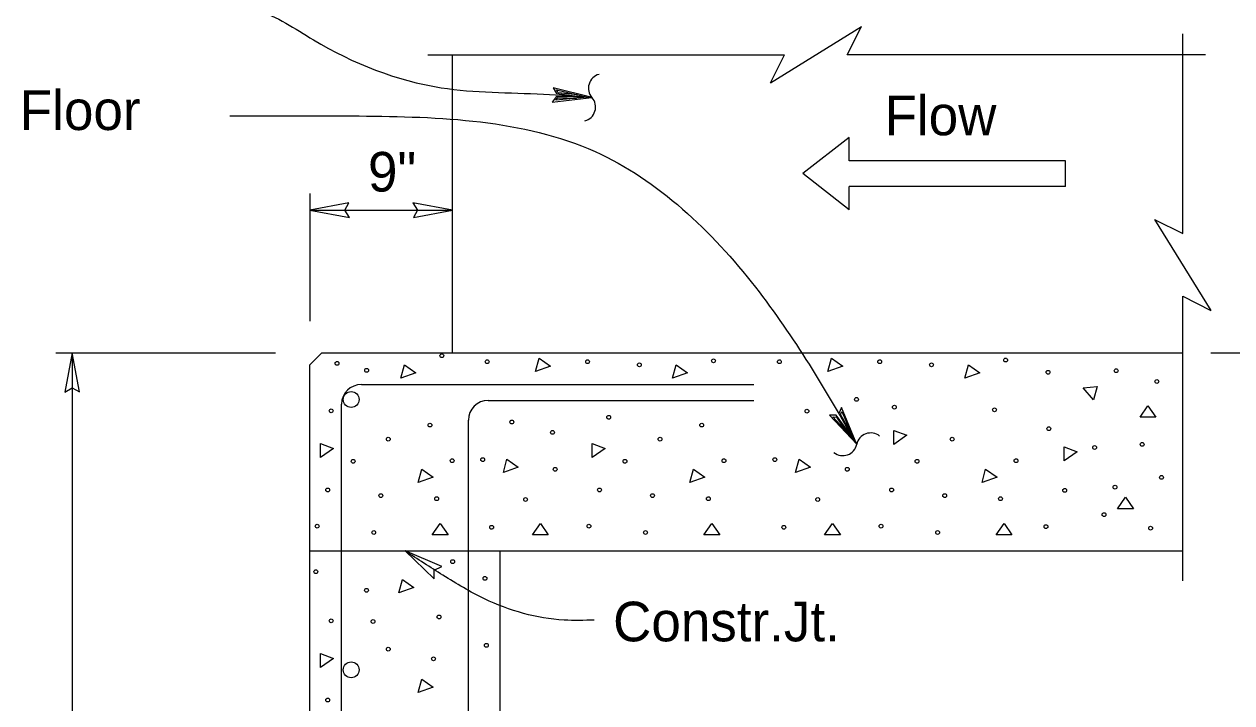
# Model space of a CAD drawing. Extents: x -0.08 to 2.83, y -0.03 to 1.92.
# Drawn here: x 1.203 to 1.5998, y 0.9512 to 1.1742 of the extents above; entities that cross this region are included whole.
import ezdxf

# ---------------------------------------------------------------- set-up
doc = ezdxf.new("R2010")
doc.units = 0
for name, color, linetype in [('50', 7, 'Continuous'), ('51', 7, 'Continuous'), ('54', 7, 'Continuous'), ('55', 7, 'Continuous'), ('57', 7, 'Continuous')]:
    doc.layers.add(name, color=color, linetype=linetype)

msp = doc.modelspace()

# ---------------------------------------------------------------- linework, layer by layer
at = {"layer": '50'}
for p, q in [((1.343748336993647, 1.066219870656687), (1.343748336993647, 1.1641173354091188)), ((1.300779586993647, 1.066219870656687), (1.296873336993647, 1.062313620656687)), ((1.300779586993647, 1.066219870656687), (1.5836677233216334, 1.066219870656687)), ((1.3710588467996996, 1.0600765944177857), (1.3722255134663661, 1.0644765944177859)), ((1.3722255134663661, 1.0644765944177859), (1.3759588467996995, 1.0618515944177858)), ((1.4670538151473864, 1.0600765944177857), (1.4682204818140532, 1.0644765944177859)), ((1.4682204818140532, 1.0644765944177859), (1.4719538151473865, 1.0618515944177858)), ((1.296873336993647, 0.6912198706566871), (1.296873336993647, 1.062313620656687)), ((1.3267968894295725, 1.0578507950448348), (1.327963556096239, 1.062250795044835)), ((1.3316968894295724, 1.059625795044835), (1.3267968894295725, 1.0578507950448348)), ((1.327963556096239, 1.062250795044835), (1.3316968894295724, 1.059625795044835)), ((1.3759588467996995, 1.0618515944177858), (1.3710588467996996, 1.0600765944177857)), ((1.4160789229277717, 1.0578507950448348), (1.4172455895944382, 1.062250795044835)), ((1.4209789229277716, 1.059625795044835), (1.4160789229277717, 1.0578507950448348)), ((1.4172455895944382, 1.062250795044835), (1.4209789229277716, 1.059625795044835)), ((1.4719538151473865, 1.0618515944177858), (1.4670538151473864, 1.0600765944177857)), ((1.5120738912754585, 1.0578507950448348), (1.5132405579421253, 1.062250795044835)), ((1.5169738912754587, 1.059625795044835), (1.5120738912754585, 1.0578507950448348)), ((1.5132405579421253, 1.062250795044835), (1.5169738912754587, 1.059625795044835)), ((1.551007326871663, 1.0547551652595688), (1.5555489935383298, 1.0551634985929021)), ((1.55434899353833, 1.0507634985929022), (1.551007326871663, 1.0547551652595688)), ((1.5555489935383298, 1.0551634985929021), (1.55434899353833, 1.0507634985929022)), ((1.5696571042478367, 1.045088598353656), (1.5722571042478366, 1.0488302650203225)), ((1.5722571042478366, 1.0488302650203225), (1.57486543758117, 1.045088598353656)), ((1.57486543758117, 1.045088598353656), (1.5696571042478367, 1.045088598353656)), ((1.4887533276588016, 1.0361190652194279), (1.488736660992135, 1.040677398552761)), ((1.488736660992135, 1.040677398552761), (1.4930199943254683, 1.0391023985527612)), ((1.3003828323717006, 1.0318357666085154), (1.300366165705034, 1.0363940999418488)), ((1.300366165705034, 1.0363940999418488), (1.3046494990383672, 1.0348190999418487)), ((1.3896648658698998, 1.0318357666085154), (1.389648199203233, 1.0363940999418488)), ((1.389648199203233, 1.0363940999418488), (1.3939315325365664, 1.0348190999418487)), ((1.4930199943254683, 1.0391023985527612), (1.4887533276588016, 1.0361190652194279)), ((1.3046494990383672, 1.0348190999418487), (1.3003828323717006, 1.0318357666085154)), ((1.3939315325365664, 1.0348190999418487), (1.3896648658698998, 1.0318357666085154)), ((1.5447260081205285, 1.0307487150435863), (1.5447093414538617, 1.0353070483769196)), ((1.5447093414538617, 1.0353070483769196), (1.5489926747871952, 1.0337320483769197)), ((1.5489926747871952, 1.0337320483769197), (1.5447260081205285, 1.0307487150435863)), ((1.3324829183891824, 1.0236061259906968), (1.333649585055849, 1.0280061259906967)), ((1.333649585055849, 1.0280061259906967), (1.3373829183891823, 1.0253811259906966)), ((1.360448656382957, 1.0268600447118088), (1.3616153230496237, 1.0312683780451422)), ((1.3653403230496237, 1.0286433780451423), (1.360448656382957, 1.0268600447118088)), ((1.3616153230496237, 1.0312683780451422), (1.3653403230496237, 1.0286433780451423)), ((1.4217649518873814, 1.0236061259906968), (1.4229316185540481, 1.0280061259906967)), ((1.4229316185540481, 1.0280061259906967), (1.4266649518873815, 1.0253811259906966)), ((1.456443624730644, 1.0268600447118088), (1.4576102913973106, 1.0312683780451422)), ((1.4613352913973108, 1.0286433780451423), (1.456443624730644, 1.0268600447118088)), ((1.4576102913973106, 1.0312683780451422), (1.4613352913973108, 1.0286433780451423)), ((1.5177599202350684, 1.0236061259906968), (1.5189265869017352, 1.0280061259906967)), ((1.5189265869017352, 1.0280061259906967), (1.5226599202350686, 1.0253811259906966)), ((1.3373829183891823, 1.0253811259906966), (1.3324829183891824, 1.0236061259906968)), ((1.4266649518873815, 1.0253811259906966), (1.4217649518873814, 1.0236061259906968)), ((1.5226599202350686, 1.0253811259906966), (1.5177599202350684, 1.0236061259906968)), ((1.5622480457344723, 1.0149934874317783), (1.5648480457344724, 1.018735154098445)), ((1.5648480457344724, 1.018735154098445), (1.5674563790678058, 1.0149934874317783)), ((1.5674563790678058, 1.0149934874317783), (1.5622480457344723, 1.0149934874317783)), ((1.3370938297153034, 1.0064281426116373), (1.3396938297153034, 1.010169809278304)), ((1.3396938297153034, 1.010169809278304), (1.3423021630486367, 1.0064281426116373)), ((1.3700158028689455, 1.0064281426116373), (1.3726158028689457, 1.010169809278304)), ((1.3726158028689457, 1.010169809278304), (1.375224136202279, 1.0064281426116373)), ((1.4263758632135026, 1.0064281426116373), (1.4289758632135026, 1.010169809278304)), ((1.4289758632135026, 1.010169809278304), (1.4315841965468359, 1.0064281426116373)), ((1.4660107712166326, 1.0064281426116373), (1.4686107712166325, 1.010169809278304)), ((1.4686107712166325, 1.010169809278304), (1.471219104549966, 1.0064281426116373)), ((1.5223708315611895, 1.0064281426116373), (1.5249708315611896, 1.010169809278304)), ((1.5249708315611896, 1.010169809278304), (1.527579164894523, 1.0064281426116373)), ((1.3423021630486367, 1.0064281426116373), (1.3370938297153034, 1.0064281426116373)), ((1.375224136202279, 1.0064281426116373), (1.3700158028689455, 1.0064281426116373)), ((1.4315841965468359, 1.0064281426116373), (1.4263758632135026, 1.0064281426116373)), ((1.471219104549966, 1.0064281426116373), (1.4660107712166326, 1.0064281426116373)), ((1.527579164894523, 1.0064281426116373), (1.5223708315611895, 1.0064281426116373)), ((1.296873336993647, 1.0011157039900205), (1.359373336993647, 1.0011157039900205)), ((1.359373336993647, 1.0011157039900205), (1.5836677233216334, 1.0011157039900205)), ((1.3593733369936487, 0.6912198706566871), (1.359373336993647, 1.0011157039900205)), ((1.3261489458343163, 0.9873208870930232), (1.3273156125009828, 0.9917208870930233)), ((1.3310489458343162, 0.9890958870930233), (1.3261489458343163, 0.9873208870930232)), ((1.3273156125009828, 0.9917208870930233), (1.3310489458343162, 0.9890958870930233)), ((1.3003828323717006, 0.9628270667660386), (1.300366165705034, 0.9673854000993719)), ((1.300366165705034, 0.9673854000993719), (1.3046494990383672, 0.9658104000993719)), ((1.3046494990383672, 0.9658104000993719), (1.3003828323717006, 0.9628270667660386)), ((1.3324829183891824, 0.9545974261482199), (1.333649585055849, 0.9589974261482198)), ((1.3373829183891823, 0.9563724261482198), (1.3324829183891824, 0.9545974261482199)), ((1.333649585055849, 0.9589974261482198), (1.3373829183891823, 0.9563724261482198))]:
    msp.add_line(p, q, dxfattribs=at)
for centre in [(1.3402182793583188, 1.0652488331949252), (1.3551425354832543, 1.0632739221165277), (1.3881219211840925, 1.0632960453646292), (1.429500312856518, 1.0635831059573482), (1.451137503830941, 1.0632739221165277), (1.4841168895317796, 1.0632960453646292), (1.5254952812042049, 1.0638210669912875), (1.30579344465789, 1.062745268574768), (1.3155124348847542, 1.0604525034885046), (1.4051387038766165, 1.0622425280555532), (1.5011336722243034, 1.0622425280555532), (1.5394304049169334, 1.0598250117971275), (1.5618039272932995, 1.0603175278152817), (1.575196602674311, 1.0567696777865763), (1.3038938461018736, 1.0471677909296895), (1.4601979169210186, 1.0470488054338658), (1.4764870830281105, 1.0509084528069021), (1.4889328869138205, 1.0483575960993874), (1.5218510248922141, 1.0474613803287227), (1.3632511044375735, 1.043479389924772), (1.3950795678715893, 1.0450261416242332), (1.3363360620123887, 1.0424641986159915), (1.376620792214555, 1.0400687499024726), (1.425618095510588, 1.0424641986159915), (1.5396757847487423, 1.0412755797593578), (1.3226443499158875, 1.0378605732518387), (1.4119263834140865, 1.0378605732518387), (1.5079213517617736, 1.0378605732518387), (1.570359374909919, 1.0361384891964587), (1.5547346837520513, 1.0350952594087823), (1.3111190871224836, 1.0305680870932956), (1.3436425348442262, 1.0307534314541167), (1.3536722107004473, 1.031114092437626), (1.3774622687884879, 1.0279488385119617), (1.4004011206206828, 1.0305680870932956), (1.4329245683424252, 1.0307534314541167), (1.4496671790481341, 1.031114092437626), (1.473457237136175, 1.0279488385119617), (1.4963960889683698, 1.0305680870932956), (1.5289195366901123, 1.0307534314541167), (1.576712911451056, 1.0252881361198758), (1.302741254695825, 1.0211511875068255), (1.320187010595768, 1.0192954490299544), (1.3920232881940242, 1.0211511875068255), (1.4094690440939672, 1.0192954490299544), (1.4880182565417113, 1.0211511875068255), (1.5054640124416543, 1.0192954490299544), (1.5449010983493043, 1.0210183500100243), (1.5614318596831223, 1.0220731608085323), (1.33853635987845, 1.0182701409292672), (1.367750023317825, 1.0180243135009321), (1.427818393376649, 1.0182701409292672), (1.463744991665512, 1.0180243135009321), (1.5238133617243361, 1.0182701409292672), (1.5578386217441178, 1.0130502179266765), (1.2992845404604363, 1.0092635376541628), (1.356594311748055, 1.0088822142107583), (1.3885665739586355, 1.0092635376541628), (1.452589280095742, 1.0088822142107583), (1.4845615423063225, 1.0092635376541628), (1.5387270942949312, 1.0091102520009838), (1.5731228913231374, 1.0085992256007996), (1.3178671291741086, 1.0071898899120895), (1.4071491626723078, 1.0071898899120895), (1.503144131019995, 1.0071898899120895), (1.3437926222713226, 0.9976017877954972), (1.2988398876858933, 0.9942873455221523), (1.3544017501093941, 0.9921030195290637), (1.3154833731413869, 0.9881943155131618), (1.3038938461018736, 0.9781590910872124), (1.3176366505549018, 0.9779584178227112), (1.339322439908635, 0.9794282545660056), (1.3226443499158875, 0.9688518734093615), (1.354863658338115, 0.9701051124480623), (1.3374831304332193, 0.9656643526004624), (1.302741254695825, 0.9521424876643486)]:
    msp.add_circle(centre, 0.0006257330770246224, dxfattribs=at)
at = {"layer": '51'}
for p, q in [((1.3138004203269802, 1.0558032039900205), (1.4427066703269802, 1.0558032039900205)), ((1.3072900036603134, 0.7120532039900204), (1.3072900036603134, 1.0492927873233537)), ((1.3554670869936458, 1.050594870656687), (1.4427066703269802, 1.050594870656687)), ((1.3489566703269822, 0.7120532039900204), (1.3489566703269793, 1.0440844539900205))]:
    msp.add_line(p, q, dxfattribs=at)
for centre in [(1.310454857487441, 1.0508614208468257), (1.310454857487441, 0.9620534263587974)]:
    msp.add_circle(centre, 0.002604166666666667, dxfattribs=at)
for centre in [(1.3138004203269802, 1.0492927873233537), (1.3554670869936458, 1.0440844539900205)]:
    msp.add_arc(centre, 0.006510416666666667, 90, 180, dxfattribs=at)
at = {"layer": '54'}
for points in [[(1.296873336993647, 1.113094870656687), (1.3098650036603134, 1.110719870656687), (1.3083566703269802, 1.113094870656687), (1.3097150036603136, 1.1154948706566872)], [(1.343748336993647, 1.113094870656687), (1.3307566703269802, 1.115469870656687), (1.3322650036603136, 1.113094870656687), (1.3309066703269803, 1.110694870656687)], [(1.218748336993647, 1.066219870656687), (1.216373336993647, 1.0532282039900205), (1.218748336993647, 1.0547365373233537), (1.2211483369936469, 1.0533782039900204)], [(1.3281555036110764, 1.0011157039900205), (1.337686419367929, 0.9919731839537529), (1.3377369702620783, 0.9947862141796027), (1.3401931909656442, 0.9960400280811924)]]:
    msp.add_lwpolyline(points, close=True, dxfattribs=at)
at = {"layer": '55'}
for p, q in [((1.4482468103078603, 1.1548715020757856), (1.4780801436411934, 1.1733694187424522)), ((1.4734582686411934, 1.1641173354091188), (1.4780801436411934, 1.1733694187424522)), ((1.5836677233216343, 1.1053734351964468), (1.5836677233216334, 1.1710349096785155)), ((1.3356639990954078, 1.1641173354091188), (1.4528718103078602, 1.1641173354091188)), ((1.4482468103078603, 1.1548715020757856), (1.4528718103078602, 1.1641173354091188)), ((1.59117128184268, 1.1641173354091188), (1.4734582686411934, 1.1641173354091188)), ((1.296873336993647, 1.1185363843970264), (1.296873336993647, 1.0765891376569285)), ((1.296873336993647, 1.113094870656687), (1.343748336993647, 1.113094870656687)), ((1.5744218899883, 1.1099984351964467), (1.5836677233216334, 1.1053734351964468)), ((1.5744218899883, 1.1099984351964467), (1.5929198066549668, 1.0801651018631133)), ((1.5836677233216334, 0.9912447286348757), (1.5836677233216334, 1.0847869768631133)), ((1.5836677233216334, 1.0847869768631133), (1.5929198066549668, 1.0801651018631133)), ((1.2133483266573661, 1.066219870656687), (1.285620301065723, 1.066219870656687)), ((1.218748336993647, 1.066219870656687), (1.2187483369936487, 0.6912198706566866)), ((1.5929198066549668, 1.066219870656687), (1.635836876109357, 1.066219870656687))]:
    msp.add_line(p, q, dxfattribs=at)
for points in [[(1.3895995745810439, 1.1500559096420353), (1.3768599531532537, 1.1533016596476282), (1.3778866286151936, 1.1513594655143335), (1.3865895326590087, 1.1502558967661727), (1.3777920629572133, 1.150355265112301), (1.3765153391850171, 1.1485641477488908), (1.3895740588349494, 1.1500493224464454)], [(1.384824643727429, 1.1509460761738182), (1.3785082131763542, 1.1516505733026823), (1.377945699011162, 1.1525749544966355), (1.3881530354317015, 1.1501560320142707), (1.3777008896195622, 1.1491587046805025), (1.3784037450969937, 1.150020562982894), (1.3844869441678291, 1.1498083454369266)], [(1.4766006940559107, 1.0361355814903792), (1.4715697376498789, 1.0482814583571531), (1.4706293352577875, 1.0462960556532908), (1.4749580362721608, 1.0386658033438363), (1.4697685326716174, 1.0457703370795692), (1.4675695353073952, 1.045719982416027), (1.476580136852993, 1.0361520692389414)], [(1.4744536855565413, 1.0404924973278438), (1.4712347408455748, 1.0459726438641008), (1.4716380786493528, 1.0469767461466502), (1.475814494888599, 1.0373539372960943), (1.4687557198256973, 1.0451266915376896), (1.4698668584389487, 1.0450800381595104), (1.4733403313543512, 1.040081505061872)]]:
    msp.add_lwpolyline(points, dxfattribs=at)
for centre, radius, start, end in [((1.3931010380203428, 1.1531520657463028), 0.004697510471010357, 104.93256697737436, 221.33863642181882), ((1.386047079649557, 1.146946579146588), 0.004697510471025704, 284.9325669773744, 41.33863642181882), ((1.4811772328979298, 1.035185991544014), 0.004697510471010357, 51.72594554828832, 168.13201499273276), ((1.4719830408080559, 1.0371181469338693), 0.004697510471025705, 231.72594554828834, 348.13201499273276)]:
    msp.add_arc(centre, radius, start, end, dxfattribs=at)
for points in [[(1.2539030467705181, 1.1808887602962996), (1.2616189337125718, 1.1808887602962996), (1.2794828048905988, 1.17885503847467), (1.2980308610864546, 1.16904959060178), (1.3399797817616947, 1.1532982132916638), (1.3736332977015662, 1.1511783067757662), (1.3895740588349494, 1.1500493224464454)], [(1.2706257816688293, 1.1440204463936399), (1.3130281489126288, 1.1440204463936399), (1.390572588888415, 1.1323226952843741), (1.4432639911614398, 1.087781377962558), (1.4765801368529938, 1.0361520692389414)], [(1.3903271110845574, 0.9783872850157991), (1.380383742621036, 0.9783872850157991), (1.3542824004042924, 0.9853757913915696), (1.3406102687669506, 0.9931407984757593), (1.3281555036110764, 1.0011157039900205)]]:
    msp.add_spline(points, degree=3, dxfattribs=at)
at = {"layer": '57'}
for p, q in [((1.4740738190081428, 1.1369184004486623), (1.4588797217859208, 1.125072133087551)), ((1.4740738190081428, 1.1292591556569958), (1.4740738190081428, 1.1369184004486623)), ((1.545158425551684, 1.1292591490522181), (1.474077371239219, 1.1292591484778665)), ((1.5451584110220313, 1.1208850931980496), (1.5451584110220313, 1.1292591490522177)), ((1.4740738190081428, 1.1132259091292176), (1.4588797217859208, 1.125072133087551)), ((1.4740738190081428, 1.1132259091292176), (1.4740738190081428, 1.1208851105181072)), ((1.545158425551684, 1.12088509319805), (1.474077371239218, 1.1208850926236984))]:
    msp.add_line(p, q, dxfattribs=at)

# ---------------------------------------------------------------- texts
for s, p in [('Floor', (1.201562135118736, 1.1394046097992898)), ('9"', (1.3159621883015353, 1.1191848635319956)), ('Constr.Jt.', (1.3965087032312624, 0.9714178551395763))]:
    msp.add_text(s, height=0.013020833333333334, dxfattribs=at).set_placement(p)
msp.add_text('Flow', height=0.013020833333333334, rotation=360, dxfattribs=at).set_placement((1.4857075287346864, 1.1376789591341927))

doc.saveas('drawing.dxf')
